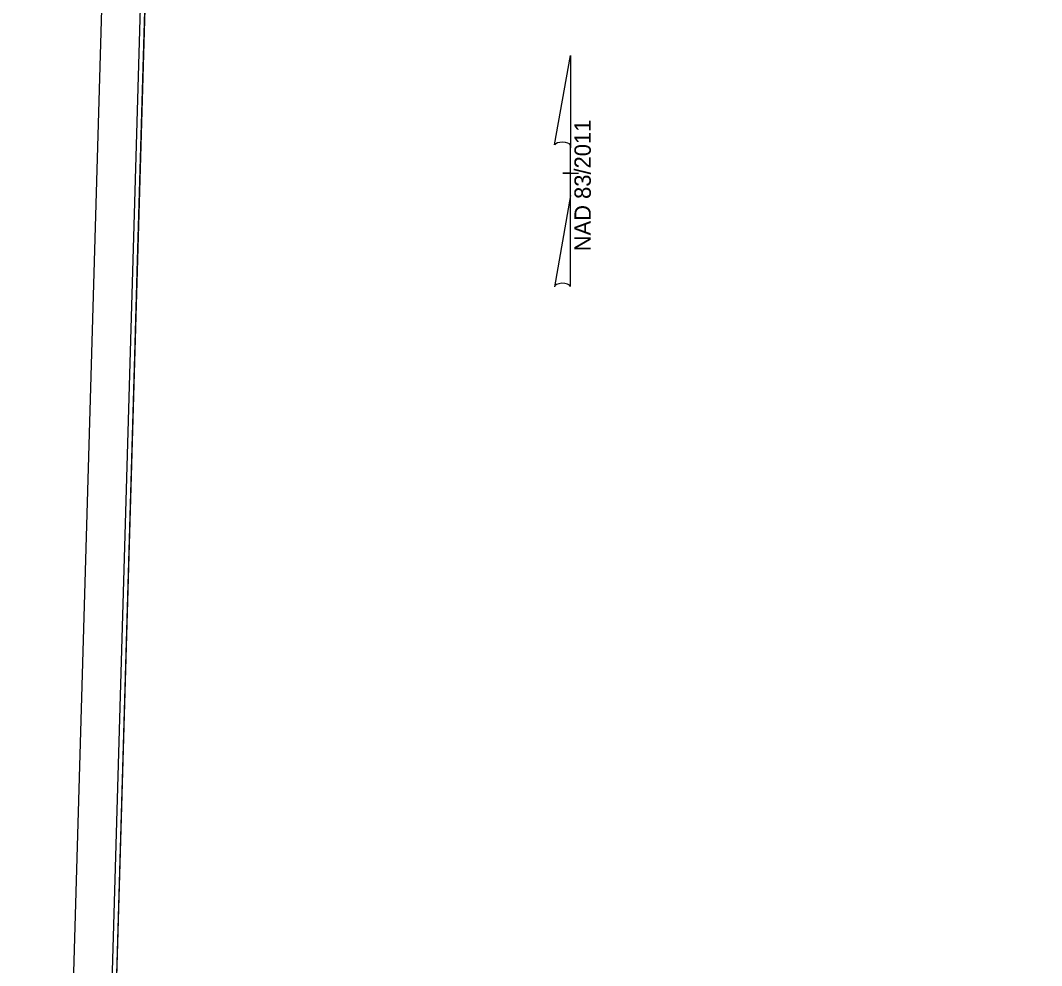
# Model space of a CAD drawing. Extents: x 2097002 to 2098146, y 685127 to 687089.
# Drawn here: x 2097002 to 2097532, y 686108 to 686598 of the extents above; entities that cross this region are included whole.
import ezdxf

# ---------------------------------------------------------------- set-up
doc = ezdxf.new("R2010")
doc.units = 0
for name, color, linetype in [('Default', 7, 'Continuous'), ('Sheet Layout Plan Border', 7, 'Continuous'), ('Sheet Plan CELL', 7, 'Continuous'), ('Sheet Plot Border Inside CELL', 7, 'Continuous'), ('Sheet Plot Border Outside CELL', 7, 'Continuous')]:
    doc.layers.add(name, color=color, linetype=linetype)

msp = doc.modelspace()

# ---------------------------------------------------------------- linework, layer by layer
at = {"layer": 'Default'}
for p, q in [((2097279.09, 686533.51), (2097287.29, 686579.86)), ((2097287.34, 686579.86), (2097287.29, 686579.86)), ((2097287.34, 686579.86), (2097287.29, 686579.86)), ((2097287.34, 686579.86), (2097287.34, 686532.06)), ((2097287.34, 686507.26), (2097287.34, 686533.46)), ((2097287.34, 686532.06), (2097287.34, 686533.41)), ((2097283.34, 686518.86), (2097283.29, 686518.86)), ((2097286.89, 686518.86), (2097283.34, 686518.86)), ((2097283.39, 686518.86), (2097291.39, 686518.86)), ((2097287.34, 686507.26), (2097278.99, 686460.01)), ((2097287.39, 686460.21), (2097287.34, 686507.26))]:
    msp.add_line(p, q, dxfattribs=at)
for centre, start_param, end_param in [((2097283.23, 686533.02), 0.216388, 2.908219), ((2097283.23, 686459.85), 0.201328, 3.141593)]:
    msp.add_ellipse(centre, major_axis=(4.23, -0.03), ratio=0.461098, start_param=start_param, end_param=end_param, dxfattribs=at)
at = {"layer": 'Sheet Layout Plan Border'}
msp.add_lwpolyline([(2098110.68, 686386.52), (2098090.85, 685704.42), (2097236.93, 685318.96), (2097029.37, 685324.99), (2097061.33, 686424.42), (2097062.77, 686473.85), (2097066.87, 686614.87), (2097306.86, 686607.89), (2097310.43, 686730.69), (2098032.53, 686709.7), (2098023.21, 686389.06)], close=True, dxfattribs=at)
at = {"layer": 'Sheet Plan CELL'}
msp.add_line((2097072.96, 686824.36), (2097029.37, 685324.98), dxfattribs=at)
at = {"layer": 'Sheet Plot Border Inside CELL'}
msp.add_lwpolyline([(2098076.98, 685140.97), (2098125.38, 686806.22), (2097070.84, 686836.88), (2097022.43, 685171.63)], close=True, dxfattribs=at)
at = {"layer": 'Sheet Plot Border Outside CELL'}
msp.add_lwpolyline([(2098096.59, 685127.4), (2098145.51, 686810.14), (2097050.98, 686841.96), (2097002.06, 685159.22)], close=True, dxfattribs=at)

# ---------------------------------------------------------------- texts
at = {"layer": 'Default'}
msp.add_text('NAD 83/2011', height=8.5, rotation=90, dxfattribs=at).set_placement((2097297.86, 686478.39))

doc.saveas('drawing.dxf')
